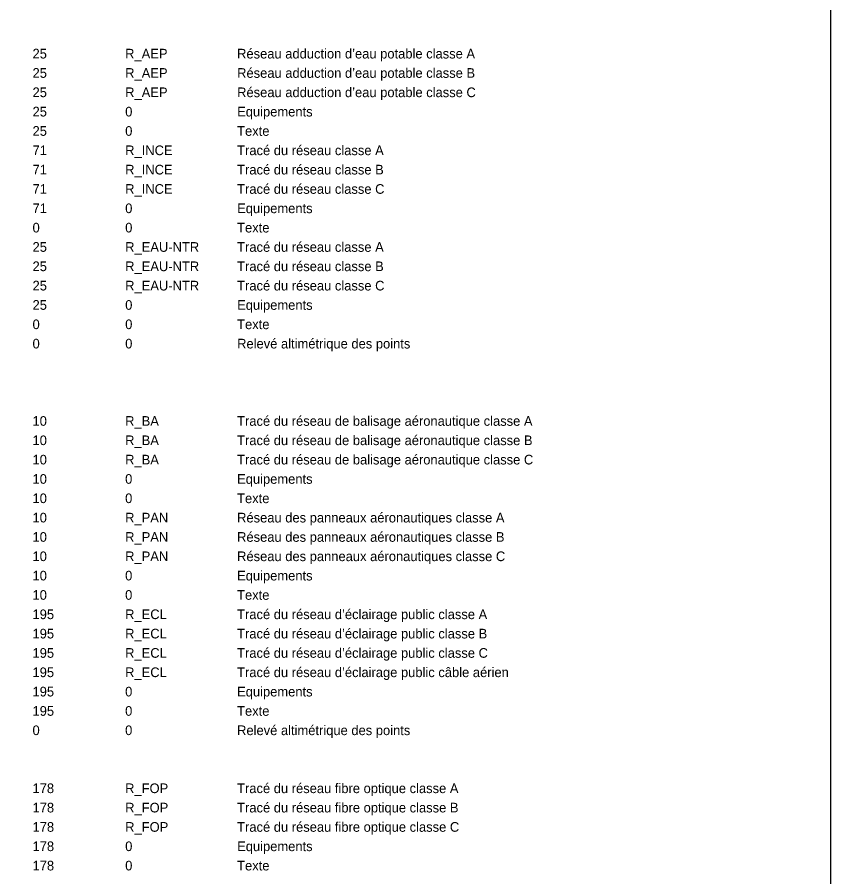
# Model space of a CAD drawing. Extents: x -60 to 214, y -380 to -21.
# Drawn here: x 72.77 to 114.84, y -245.94 to -201.47 of the extents above; entities that cross this region are included whole.
import ezdxf

# ---------------------------------------------------------------- set-up
doc = ezdxf.new("R2010")
doc.units = 0
for name, color, linetype in [('Default', 7, 'Continuous'), ('DH_TEXTE', 7, 'Continuous'), ('R_CF_FO_CANALISATION_CL_A', 7, 'Continuous'), ('R_CF_FO_CANALISATION_CL_B', 7, 'Continuous'), ('R_CF_FO_CANALISATION_CL_C', 7, 'Continuous'), ('R_CF_FO_EQUIP', 7, 'Continuous'), ('R_CF_FO_TEXTE', 7, 'Continuous'), ('R_ECLAIR_AERO_EQUIP', 7, 'Continuous'), ('R_ECLAIR_AERO_LIAISON_CL_A', 7, 'Continuous'), ('R_ECLAIR_AERO_LIAISON_CL_B', 7, 'Continuous'), ('R_ECLAIR_AERO_LIAISON_CL_C', 7, 'Continuous'), ('R_ECLAIR_AERO_TEXTE', 7, 'Continuous'), ('R_ECLAIR_ALT_POINT', 7, 'Continuous'), ('R_ECLAIR_PANNEAU_AERO_EQUIP', 7, 'Continuous'), ('R_ECLAIR_PANNEAU_AERO_LIAISON_CL_A', 7, 'Continuous'), ('R_ECLAIR_PANNEAU_AERO_LIAISON_CL_B', 7, 'Continuous'), ('R_ECLAIR_PANNEAU_AERO_LIAISON_CL_C', 7, 'Continuous'), ('R_ECLAIR_PANNEAU_AERO_TEXTE', 7, 'Continuous'), ('R_ECLAIR_PUB_EQUIP', 7, 'Continuous'), ('R_ECLAIR_PUB_LIAISON_CL_A', 7, 'Continuous'), ('R_ECLAIR_PUB_LIAISON_CL_B', 7, 'Continuous'), ('R_ECLAIR_PUB_LIAISON_CL_C', 7, 'Continuous'), ('R_ECLAIR_PUB_TEXTE', 7, 'Continuous'), ('R_EPR_AEP_CANALISATION_CL_A', 7, 'Continuous'), ('R_EPR_AEP_CANALISATION_CL_B', 7, 'Continuous'), ('R_EPR_AEP_CANALISATION_CL_C', 7, 'Continuous'), ('R_EPR_AEP_EQUIP', 7, 'Continuous'), ('R_EPR_AEP_TEXTE', 7, 'Continuous'), ('R_EPR_EAU_NON_TRAITEE_CANALISATION_CL_A', 7, 'Continuous'), ('R_EPR_EAU_NON_TRAITEE_CANALISATION_CL_B', 7, 'Continuous'), ('R_EPR_EAU_NON_TRAITEE_CANALISATION_CL_C', 7, 'Continuous'), ('R_EPR_EAU_NON_TRAITEE_EQUIP', 7, 'Continuous'), ('R_EPR_EAU_NON_TRAITEE_TEXTE', 7, 'Continuous'), ('R_EPR_EAU_PROPRE_ALT_POINT', 7, 'Continuous'), ('R_EPR_INCENDIE_CANALISATION_CL_A', 7, 'Continuous'), ('R_EPR_INCENDIE_CANALISATION_CL_B', 7, 'Continuous'), ('R_EPR_INCENDIE_CANALISATION_CL_C', 7, 'Continuous'), ('R_EPR_INCENDIE_EQUIP', 7, 'Continuous'), ('R_EPR_INCENDIE_TEXTE', 7, 'Continuous')]:
    doc.layers.add(name, color=color, linetype=linetype)

msp = doc.modelspace()

# ---------------------------------------------------------------- linework, layer by layer
at = {"layer": 'Default'}
msp.add_lwpolyline([(114.838, -25.727), (33.073, -25.727), (33.073, -380.216), (114.838, -380.216)], close=True, dxfattribs=at)

# ---------------------------------------------------------------- texts
at = {"layer": 'DH_TEXTE'}
for s, p in [('195 ', (73.559, -235.61)), ('R_ECL ', (78.348, -235.61)), ('Tracé du réseau d’éclairage public câble aérien ', (84.138, -235.61))]:
    msp.add_text(s, height=0.5, dxfattribs=at).set_placement(p)
at = {"layer": 'R_CF_FO_CANALISATION_CL_A'}
for s, p in [('178 ', (73.559, -241.61)), ('R_FOP ', (78.348, -241.61)), ('Tracé du réseau fibre optique classe A ', (84.138, -241.61))]:
    msp.add_text(s, height=0.5, dxfattribs=at).set_placement(p)
at = {"layer": 'R_CF_FO_CANALISATION_CL_B'}
for s, p in [('178 ', (73.561, -242.61)), ('R_FOP ', (78.351, -242.61)), ('Tracé du réseau fibre optique classe B ', (84.14, -242.61))]:
    msp.add_text(s, height=0.5, dxfattribs=at).set_placement(p)
at = {"layer": 'R_CF_FO_CANALISATION_CL_C'}
for s, p in [('178 ', (73.561, -243.61)), ('R_FOP ', (78.351, -243.61)), ('Tracé du réseau fibre optique classe C ', (84.14, -243.61))]:
    msp.add_text(s, height=0.5, dxfattribs=at).set_placement(p)
at = {"layer": 'R_CF_FO_EQUIP'}
for s, p in [('178 ', (73.561, -244.61)), ('0 ', (78.351, -244.61)), ('Equipements ', (84.14, -244.61))]:
    msp.add_text(s, height=0.5, dxfattribs=at).set_placement(p)
at = {"layer": 'R_CF_FO_TEXTE'}
for s, p in [('178 ', (73.561, -245.61)), ('0 ', (78.351, -245.61)), ('Texte ', (84.14, -245.61))]:
    msp.add_text(s, height=0.5, dxfattribs=at).set_placement(p)
at = {"layer": 'R_ECLAIR_AERO_EQUIP'}
for s, p in [('10 ', (73.559, -225.61)), ('0 ', (78.348, -225.61)), ('Equipements ', (84.138, -225.61))]:
    msp.add_text(s, height=0.5, dxfattribs=at).set_placement(p)
at = {"layer": 'R_ECLAIR_AERO_LIAISON_CL_A'}
for s, p in [('10 ', (73.559, -222.61)), ('R_BA ', (78.348, -222.61)), ('Tracé du réseau de balisage aéronautique classe A ', (84.138, -222.61))]:
    msp.add_text(s, height=0.5, dxfattribs=at).set_placement(p)
at = {"layer": 'R_ECLAIR_AERO_LIAISON_CL_B'}
for s, p in [('10 ', (73.559, -223.61)), ('R_BA ', (78.348, -223.61)), ('Tracé du réseau de balisage aéronautique classe B ', (84.138, -223.61))]:
    msp.add_text(s, height=0.5, dxfattribs=at).set_placement(p)
at = {"layer": 'R_ECLAIR_AERO_LIAISON_CL_C'}
for s, p in [('10 ', (73.559, -224.61)), ('Tracé du réseau de balisage aéronautique classe C ', (84.138, -224.61)), ('R_BA ', (78.348, -224.61))]:
    msp.add_text(s, height=0.5, dxfattribs=at).set_placement(p)
at = {"layer": 'R_ECLAIR_AERO_TEXTE'}
for s, p in [('10 ', (73.559, -226.61)), ('0 ', (78.348, -226.61)), ('Texte ', (84.138, -226.61))]:
    msp.add_text(s, height=0.5, dxfattribs=at).set_placement(p)
at = {"layer": 'R_ECLAIR_ALT_POINT'}
for s, p in [('0 ', (73.559, -238.61)), ('0 ', (78.348, -238.61)), ('Relevé altimétrique des points ', (84.138, -238.61))]:
    msp.add_text(s, height=0.5, dxfattribs=at).set_placement(p)
at = {"layer": 'R_ECLAIR_PANNEAU_AERO_EQUIP'}
for s, p in [('10 ', (73.559, -230.61)), ('0 ', (78.348, -230.61)), ('Equipements ', (84.138, -230.61))]:
    msp.add_text(s, height=0.5, dxfattribs=at).set_placement(p)
at = {"layer": 'R_ECLAIR_PANNEAU_AERO_LIAISON_CL_A'}
for s, p in [('10 ', (73.559, -227.61)), ('R_PAN ', (78.348, -227.61)), ('Réseau des panneaux aéronautiques classe A ', (84.138, -227.61))]:
    msp.add_text(s, height=0.5, dxfattribs=at).set_placement(p)
at = {"layer": 'R_ECLAIR_PANNEAU_AERO_LIAISON_CL_B'}
for s, p in [('10 ', (73.559, -228.61)), ('Réseau des panneaux aéronautiques classe B ', (84.138, -228.61)), ('R_PAN ', (78.348, -228.61))]:
    msp.add_text(s, height=0.5, dxfattribs=at).set_placement(p)
at = {"layer": 'R_ECLAIR_PANNEAU_AERO_LIAISON_CL_C'}
for s, p in [('10 ', (73.559, -229.61)), ('R_PAN ', (78.348, -229.61)), ('Réseau des panneaux aéronautiques classe C ', (84.138, -229.61))]:
    msp.add_text(s, height=0.5, dxfattribs=at).set_placement(p)
at = {"layer": 'R_ECLAIR_PANNEAU_AERO_TEXTE'}
for s, p in [('10 ', (73.559, -231.61)), ('0 ', (78.348, -231.61)), ('Texte ', (84.138, -231.61))]:
    msp.add_text(s, height=0.5, dxfattribs=at).set_placement(p)
at = {"layer": 'R_ECLAIR_PUB_EQUIP'}
for s, p in [('195 ', (73.559, -236.61)), ('0 ', (78.348, -236.61)), ('Equipements ', (84.138, -236.61))]:
    msp.add_text(s, height=0.5, dxfattribs=at).set_placement(p)
at = {"layer": 'R_ECLAIR_PUB_LIAISON_CL_A'}
for s, p in [('195 ', (73.559, -232.61)), ('R_ECL ', (78.348, -232.61)), ('Tracé du réseau d’éclairage public classe A ', (84.138, -232.61))]:
    msp.add_text(s, height=0.5, dxfattribs=at).set_placement(p)
at = {"layer": 'R_ECLAIR_PUB_LIAISON_CL_B'}
for s, p in [('195 ', (73.559, -233.61)), ('R_ECL ', (78.348, -233.61)), ('Tracé du réseau d’éclairage public classe B ', (84.138, -233.61))]:
    msp.add_text(s, height=0.5, dxfattribs=at).set_placement(p)
at = {"layer": 'R_ECLAIR_PUB_LIAISON_CL_C'}
for s, p in [('195 ', (73.559, -234.61)), ('R_ECL ', (78.348, -234.61)), ('Tracé du réseau d’éclairage public classe C ', (84.138, -234.61))]:
    msp.add_text(s, height=0.5, dxfattribs=at).set_placement(p)
at = {"layer": 'R_ECLAIR_PUB_TEXTE'}
for s, p in [('195 ', (73.559, -237.61)), ('0 ', (78.348, -237.61)), ('Texte ', (84.138, -237.61))]:
    msp.add_text(s, height=0.5, dxfattribs=at).set_placement(p)
at = {"layer": 'R_EPR_AEP_CANALISATION_CL_A'}
for s, p in [('25 ', (73.559, -203.61)), ('R_AEP ', (78.348, -203.61)), ('Réseau adduction d’eau potable classe A ', (84.138, -203.61))]:
    msp.add_text(s, height=0.5, dxfattribs=at).set_placement(p)
at = {"layer": 'R_EPR_AEP_CANALISATION_CL_B'}
for s, p in [('Réseau adduction d’eau potable classe B ', (84.14, -204.61)), ('25 ', (73.561, -204.61)), ('R_AEP ', (78.351, -204.61))]:
    msp.add_text(s, height=0.5, dxfattribs=at).set_placement(p)
at = {"layer": 'R_EPR_AEP_CANALISATION_CL_C'}
for s, p in [('25 ', (73.561, -205.61)), ('R_AEP ', (78.351, -205.61)), ('Réseau adduction d’eau potable classe C ', (84.14, -205.61))]:
    msp.add_text(s, height=0.5, dxfattribs=at).set_placement(p)
at = {"layer": 'R_EPR_AEP_EQUIP'}
for s, p in [('25 ', (73.561, -206.61)), ('0 ', (78.351, -206.61)), ('Equipements ', (84.14, -206.61))]:
    msp.add_text(s, height=0.5, dxfattribs=at).set_placement(p)
at = {"layer": 'R_EPR_AEP_TEXTE'}
for s, p in [('25 ', (73.561, -207.61)), ('0 ', (78.351, -207.61)), ('Texte ', (84.14, -207.61))]:
    msp.add_text(s, height=0.5, dxfattribs=at).set_placement(p)
at = {"layer": 'R_EPR_EAU_NON_TRAITEE_CANALISATION_CL_A'}
for s, p in [('25 ', (73.561, -213.61)), ('R_EAU-NTR ', (78.351, -213.61)), ('Tracé du réseau classe A ', (84.14, -213.61))]:
    msp.add_text(s, height=0.5, dxfattribs=at).set_placement(p)
at = {"layer": 'R_EPR_EAU_NON_TRAITEE_CANALISATION_CL_B'}
for s, p in [('25 ', (73.561, -214.61)), ('R_EAU-NTR ', (78.351, -214.61)), ('Tracé du réseau classe B ', (84.14, -214.61))]:
    msp.add_text(s, height=0.5, dxfattribs=at).set_placement(p)
at = {"layer": 'R_EPR_EAU_NON_TRAITEE_CANALISATION_CL_C'}
for s, p in [('25 ', (73.561, -215.61)), ('R_EAU-NTR ', (78.351, -215.61)), ('Tracé du réseau classe C ', (84.14, -215.61))]:
    msp.add_text(s, height=0.5, dxfattribs=at).set_placement(p)
at = {"layer": 'R_EPR_EAU_NON_TRAITEE_EQUIP'}
for s, p in [('Equipements ', (84.14, -216.61)), ('25 ', (73.561, -216.61)), ('0 ', (78.351, -216.61))]:
    msp.add_text(s, height=0.5, dxfattribs=at).set_placement(p)
at = {"layer": 'R_EPR_EAU_NON_TRAITEE_TEXTE'}
for s, p in [('0', (73.561, -217.61)), ('0 ', (78.351, -217.61)), ('Texte ', (84.14, -217.61))]:
    msp.add_text(s, height=0.5, dxfattribs=at).set_placement(p)
at = {"layer": 'R_EPR_EAU_PROPRE_ALT_POINT'}
for s, p in [('0 ', (73.561, -218.61)), ('0 ', (78.351, -218.61)), ('Relevé altimétrique des points ', (84.14, -218.61))]:
    msp.add_text(s, height=0.5, dxfattribs=at).set_placement(p)
at = {"layer": 'R_EPR_INCENDIE_CANALISATION_CL_A'}
for s, p in [('Tracé du réseau classe A ', (84.14, -208.61)), ('71 ', (73.561, -208.61)), ('R_INCE ', (78.351, -208.61))]:
    msp.add_text(s, height=0.5, dxfattribs=at).set_placement(p)
at = {"layer": 'R_EPR_INCENDIE_CANALISATION_CL_B'}
for s, p in [('71 ', (73.561, -209.61)), ('R_INCE ', (78.351, -209.61)), ('Tracé du réseau classe B ', (84.14, -209.61))]:
    msp.add_text(s, height=0.5, dxfattribs=at).set_placement(p)
at = {"layer": 'R_EPR_INCENDIE_CANALISATION_CL_C'}
for s, p in [('71 ', (73.561, -210.61)), ('R_INCE ', (78.351, -210.61)), ('Tracé du réseau classe C ', (84.14, -210.61))]:
    msp.add_text(s, height=0.5, dxfattribs=at).set_placement(p)
at = {"layer": 'R_EPR_INCENDIE_EQUIP'}
for s, p in [('71 ', (73.561, -211.61)), ('0 ', (78.351, -211.61)), ('Equipements ', (84.14, -211.61))]:
    msp.add_text(s, height=0.5, dxfattribs=at).set_placement(p)
at = {"layer": 'R_EPR_INCENDIE_TEXTE'}
for s, p in [('0', (73.561, -212.61)), ('0 ', (78.351, -212.61)), ('Texte ', (84.14, -212.61))]:
    msp.add_text(s, height=0.5, dxfattribs=at).set_placement(p)

doc.saveas('drawing.dxf')
